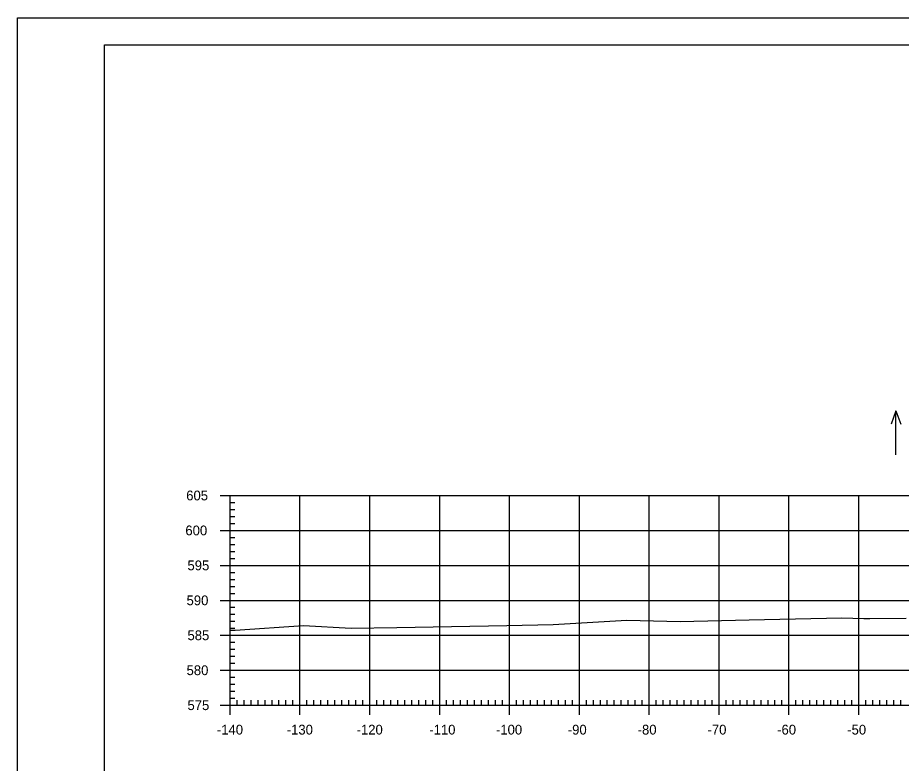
# Model space of a CAD drawing. Extents: x 961436 to 1372525, y 380079 to 2027791.
# Drawn here: x 1370463.4 to 1370589.9, y 380215.7 to 380322.4 of the extents above; entities that cross this region are included whole.
import ezdxf

# ---------------------------------------------------------------- set-up
doc = ezdxf.new("R2010")
doc.units = 0
for name, color, linetype in [('R_Axis', 7, 'Continuous'), ('R_Axis Annot', 7, 'Continuous'), ('R_Exist Surface', 7, 'Continuous'), ('R_Grid', 7, 'Continuous'), ('R_No Plot', 7, 'Continuous'), ('R_Water Annot', 7, 'Continuous')]:
    doc.layers.add(name, color=color, linetype=linetype)

msp = doc.modelspace()

# ---------------------------------------------------------------- linework, layer by layer
at = {"layer": 'R_Axis'}
for p, q in [((1370492.41, 380254.06), (1370495.21, 380254.06)), ((1370493.81, 380224.06), (1370493.81, 380254.06)), ((1370493.81, 380253.06), (1370494.51, 380253.06)), ((1370493.81, 380252.06), (1370494.51, 380252.06)), ((1370493.81, 380251.06), (1370494.51, 380251.06)), ((1370492.41, 380249.06), (1370495.21, 380249.06)), ((1370493.81, 380250.06), (1370494.51, 380250.06)), ((1370493.81, 380248.06), (1370494.51, 380248.06)), ((1370493.81, 380247.06), (1370494.51, 380247.06)), ((1370493.81, 380246.06), (1370494.51, 380246.06)), ((1370492.41, 380244.06), (1370495.21, 380244.06)), ((1370493.81, 380245.06), (1370494.51, 380245.06)), ((1370493.81, 380243.06), (1370494.51, 380243.06)), ((1370493.81, 380242.06), (1370494.51, 380242.06)), ((1370493.81, 380241.06), (1370494.51, 380241.06)), ((1370493.81, 380240.06), (1370494.51, 380240.06)), ((1370492.41, 380239.06), (1370495.21, 380239.06)), ((1370493.81, 380238.06), (1370494.51, 380238.06)), ((1370493.81, 380237.06), (1370494.51, 380237.06)), ((1370493.81, 380236.06), (1370494.51, 380236.06)), ((1370493.81, 380235.06), (1370494.51, 380235.06)), ((1370492.41, 380234.06), (1370495.21, 380234.06)), ((1370493.81, 380233.06), (1370494.51, 380233.06)), ((1370493.81, 380232.06), (1370494.51, 380232.06)), ((1370493.81, 380231.06), (1370494.51, 380231.06)), ((1370493.81, 380230.06), (1370494.51, 380230.06)), ((1370492.41, 380229.06), (1370495.21, 380229.06)), ((1370493.81, 380228.06), (1370494.51, 380228.06)), ((1370493.81, 380227.06), (1370494.51, 380227.06)), ((1370493.81, 380226.06), (1370494.51, 380226.06)), ((1370493.81, 380222.66), (1370493.81, 380225.46)), ((1370493.81, 380225.06), (1370494.51, 380225.06)), ((1370503.81, 380222.66), (1370503.81, 380225.46)), ((1370513.81, 380222.66), (1370513.81, 380225.46)), ((1370523.81, 380222.66), (1370523.81, 380225.46)), ((1370533.81, 380222.66), (1370533.81, 380225.46)), ((1370543.81, 380222.66), (1370543.81, 380225.46)), ((1370553.81, 380222.66), (1370553.81, 380225.46)), ((1370563.81, 380222.66), (1370563.81, 380225.46)), ((1370573.81, 380222.66), (1370573.81, 380225.46)), ((1370583.81, 380222.66), (1370583.81, 380225.46)), ((1370492.41, 380224.06), (1370495.21, 380224.06)), ((1370493.81, 380224.06), (1370773.81, 380224.06)), ((1370494.81, 380224.06), (1370494.81, 380224.76)), ((1370495.81, 380224.06), (1370495.81, 380224.76)), ((1370496.81, 380224.06), (1370496.81, 380224.76)), ((1370497.81, 380224.06), (1370497.81, 380224.76)), ((1370498.81, 380224.06), (1370498.81, 380224.76)), ((1370499.81, 380224.06), (1370499.81, 380224.76)), ((1370500.81, 380224.06), (1370500.81, 380224.76)), ((1370501.81, 380224.06), (1370501.81, 380224.76)), ((1370502.81, 380224.06), (1370502.81, 380224.76)), ((1370504.81, 380224.06), (1370504.81, 380224.76)), ((1370505.81, 380224.06), (1370505.81, 380224.76)), ((1370506.81, 380224.06), (1370506.81, 380224.76)), ((1370507.81, 380224.06), (1370507.81, 380224.76)), ((1370508.81, 380224.06), (1370508.81, 380224.76)), ((1370509.81, 380224.06), (1370509.81, 380224.76)), ((1370510.81, 380224.06), (1370510.81, 380224.76)), ((1370511.81, 380224.06), (1370511.81, 380224.76)), ((1370512.81, 380224.06), (1370512.81, 380224.76)), ((1370514.81, 380224.06), (1370514.81, 380224.76)), ((1370515.81, 380224.06), (1370515.81, 380224.76)), ((1370516.81, 380224.06), (1370516.81, 380224.76)), ((1370517.81, 380224.06), (1370517.81, 380224.76)), ((1370518.81, 380224.06), (1370518.81, 380224.76)), ((1370519.81, 380224.06), (1370519.81, 380224.76)), ((1370520.81, 380224.06), (1370520.81, 380224.76)), ((1370521.81, 380224.06), (1370521.81, 380224.76)), ((1370522.81, 380224.06), (1370522.81, 380224.76)), ((1370524.81, 380224.06), (1370524.81, 380224.76)), ((1370525.81, 380224.06), (1370525.81, 380224.76)), ((1370526.81, 380224.06), (1370526.81, 380224.76)), ((1370527.81, 380224.06), (1370527.81, 380224.76)), ((1370528.81, 380224.06), (1370528.81, 380224.76)), ((1370529.81, 380224.06), (1370529.81, 380224.76)), ((1370530.81, 380224.06), (1370530.81, 380224.76)), ((1370531.81, 380224.06), (1370531.81, 380224.76)), ((1370532.81, 380224.06), (1370532.81, 380224.76)), ((1370534.81, 380224.06), (1370534.81, 380224.76)), ((1370535.81, 380224.06), (1370535.81, 380224.76)), ((1370536.81, 380224.06), (1370536.81, 380224.76)), ((1370537.81, 380224.06), (1370537.81, 380224.76)), ((1370538.81, 380224.06), (1370538.81, 380224.76)), ((1370539.81, 380224.06), (1370539.81, 380224.76)), ((1370540.81, 380224.06), (1370540.81, 380224.76)), ((1370541.81, 380224.06), (1370541.81, 380224.76)), ((1370542.81, 380224.06), (1370542.81, 380224.76)), ((1370544.81, 380224.06), (1370544.81, 380224.76)), ((1370545.81, 380224.06), (1370545.81, 380224.76)), ((1370546.81, 380224.06), (1370546.81, 380224.76)), ((1370547.81, 380224.06), (1370547.81, 380224.76)), ((1370548.81, 380224.06), (1370548.81, 380224.76)), ((1370549.81, 380224.06), (1370549.81, 380224.76)), ((1370550.81, 380224.06), (1370550.81, 380224.76)), ((1370551.81, 380224.06), (1370551.81, 380224.76)), ((1370552.81, 380224.06), (1370552.81, 380224.76)), ((1370554.81, 380224.06), (1370554.81, 380224.76)), ((1370555.81, 380224.06), (1370555.81, 380224.76)), ((1370556.81, 380224.06), (1370556.81, 380224.76)), ((1370557.81, 380224.06), (1370557.81, 380224.76)), ((1370558.81, 380224.06), (1370558.81, 380224.76)), ((1370559.81, 380224.06), (1370559.81, 380224.76)), ((1370560.81, 380224.06), (1370560.81, 380224.76)), ((1370561.81, 380224.06), (1370561.81, 380224.76)), ((1370562.81, 380224.06), (1370562.81, 380224.76)), ((1370564.81, 380224.06), (1370564.81, 380224.76)), ((1370565.81, 380224.06), (1370565.81, 380224.76)), ((1370566.81, 380224.06), (1370566.81, 380224.76)), ((1370567.81, 380224.06), (1370567.81, 380224.76)), ((1370568.81, 380224.06), (1370568.81, 380224.76)), ((1370569.81, 380224.06), (1370569.81, 380224.76)), ((1370570.81, 380224.06), (1370570.81, 380224.76)), ((1370571.81, 380224.06), (1370571.81, 380224.76)), ((1370572.81, 380224.06), (1370572.81, 380224.76)), ((1370574.81, 380224.06), (1370574.81, 380224.76)), ((1370575.81, 380224.06), (1370575.81, 380224.76)), ((1370576.81, 380224.06), (1370576.81, 380224.76)), ((1370577.81, 380224.06), (1370577.81, 380224.76)), ((1370578.81, 380224.06), (1370578.81, 380224.76)), ((1370579.81, 380224.06), (1370579.81, 380224.76)), ((1370580.81, 380224.06), (1370580.81, 380224.76)), ((1370581.81, 380224.06), (1370581.81, 380224.76)), ((1370582.81, 380224.06), (1370582.81, 380224.76)), ((1370584.81, 380224.06), (1370584.81, 380224.76)), ((1370585.81, 380224.06), (1370585.81, 380224.76)), ((1370586.81, 380224.06), (1370586.81, 380224.76)), ((1370587.81, 380224.06), (1370587.81, 380224.76)), ((1370588.81, 380224.06), (1370588.81, 380224.76)), ((1370589.81, 380224.06), (1370589.81, 380224.76))]:
    msp.add_line(p, q, dxfattribs=at)
at = {"layer": 'R_Exist Surface'}
msp.add_lwpolyline([(1370493.81, 380234.77), (1370494.56, 380234.77), (1370504.3, 380235.44), (1370511.16, 380235.06), (1370517.67, 380235.17), (1370525.49, 380235.33), (1370533.43, 380235.47), (1370540.07, 380235.61), (1370550.62, 380236.23), (1370558.25, 380236.01), (1370568.13, 380236.25), (1370570.32, 380236.32), (1370581.39, 380236.58), (1370584.53, 380236.47), (1370585.4, 380236.48), (1370590.6, 380236.52)], dxfattribs=at)
at = {"layer": 'R_Grid'}
for p, q in [((1370493.81, 380254.06), (1370773.81, 380254.06)), ((1370493.81, 380224.06), (1370493.81, 380254.06)), ((1370503.81, 380224.06), (1370503.81, 380254.06)), ((1370513.81, 380224.06), (1370513.81, 380254.06)), ((1370523.81, 380224.06), (1370523.81, 380254.06)), ((1370533.81, 380224.06), (1370533.81, 380254.06)), ((1370543.81, 380224.06), (1370543.81, 380254.06)), ((1370553.81, 380224.06), (1370553.81, 380254.06)), ((1370563.81, 380224.06), (1370563.81, 380254.06)), ((1370573.81, 380224.06), (1370573.81, 380254.06)), ((1370583.81, 380224.06), (1370583.81, 380254.06)), ((1370493.81, 380249.06), (1370773.81, 380249.06)), ((1370493.81, 380244.06), (1370773.81, 380244.06)), ((1370493.81, 380239.06), (1370773.81, 380239.06)), ((1370493.81, 380234.06), (1370773.81, 380234.06)), ((1370493.81, 380229.06), (1370773.81, 380229.06)), ((1370493.81, 380224.06), (1370773.81, 380224.06))]:
    msp.add_line(p, q, dxfattribs=at)
at = {"layer": 'R_No Plot'}
for p, q in [((1370463.41, 380322.41), (1370796.74, 380322.41)), ((1370475.81, 380318.52), (1370791.99, 380318.52)), ((1370475.81, 380113.06), (1370475.81, 380318.52))]:
    msp.add_line(p, q, dxfattribs=at)
for points in [[(1370463.4, 380322.41), (1370796.74, 380322.41), (1370796.74, 380109.08), (1370463.4, 380109.08)], [(1370709.73, 380318.52), (1370729.35, 380318.52), (1370729.35, 380308.64), (1370745.46, 380308.64), (1370768.66, 380308.64), (1370768.78, 380280.48), (1370791.99, 380280.48), (1370791.99, 380113.06), (1370475.81, 380113.06), (1370475.81, 380318.52)]]:
    msp.add_lwpolyline(points, close=True, dxfattribs=at)
at = {"layer": 'R_Water Annot'}
for p, q in [((1370589.12, 380266.16), (1370588.42, 380264.24)), ((1370589.12, 380259.88), (1370589.12, 380266.16)), ((1370589.12, 380266.16), (1370589.82, 380264.24))]:
    msp.add_line(p, q, dxfattribs=at)

# ---------------------------------------------------------------- texts
at = {"layer": 'R_Axis Annot'}
for s, p in [('605', (1370487.53, 380253.36)), ('600', (1370487.41, 380248.36)), ('595', (1370487.71, 380243.36)), ('590', (1370487.58, 380238.36)), ('585', (1370487.71, 380233.36)), ('580', (1370487.58, 380228.36)), ('575', (1370487.71, 380223.36)), ('-140', (1370491.92, 380219.86)), ('-130', (1370501.92, 380219.86)), ('-120', (1370511.92, 380219.86)), ('-110', (1370522.32, 380219.86)), ('-100', (1370531.87, 380219.86)), ('-90', (1370542.15, 380219.86)), ('-80', (1370552.15, 380219.86)), ('-70', (1370562.15, 380219.86)), ('-60', (1370572.12, 380219.86)), ('-50', (1370582.15, 380219.86))]:
    msp.add_text(s, height=1.4, dxfattribs=at).set_placement(p)

doc.saveas('drawing.dxf')
